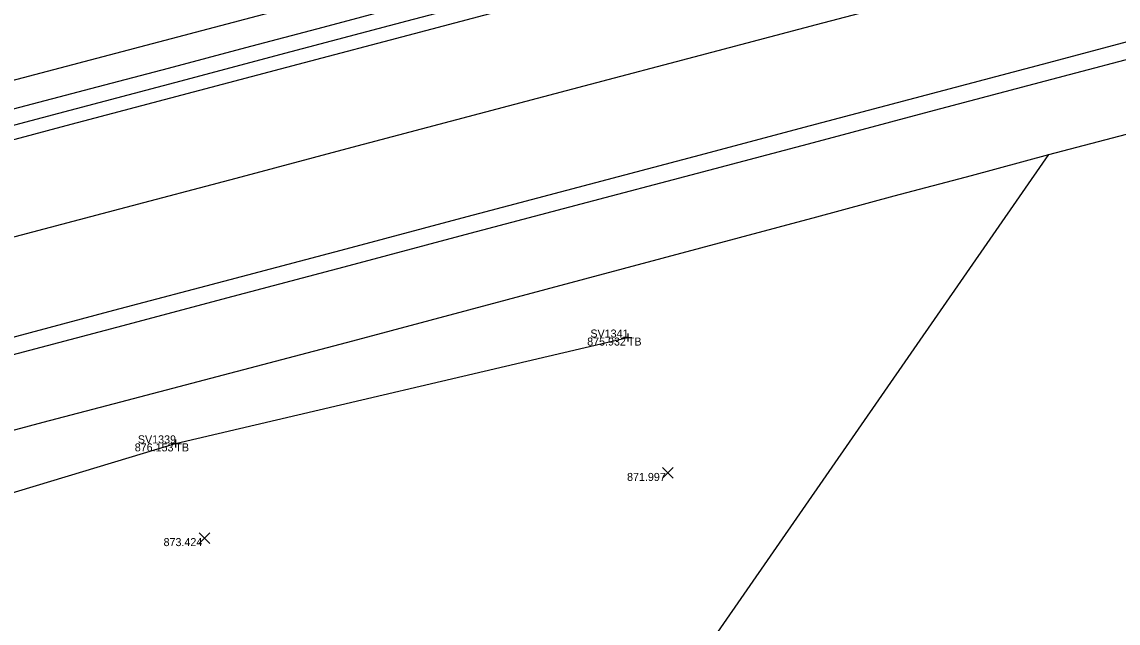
# Model space of a CAD drawing. Extents: x 2125299 to 2129212, y 713100 to 714300.
# Drawn here: x 2128517.6 to 2128654.5, y 713974 to 714049.1 of the extents above; entities that cross this region are included whole.
import ezdxf

# ---------------------------------------------------------------- set-up
doc = ezdxf.new("R2010")
doc.units = 0
for name, color, linetype in [('_CIVIL_CONSTRUCTION', 7, 'Continuous'), ('DT_X_Terrain_Boundary', 7, 'Continuous'), ('PV_X_EOP', 7, 'Continuous'), ('PV_X_Shoulder_Rumble_Strip', 7, 'Continuous'), ('RW_P_Esmt_TMP', 7, 'Continuous'), ('RW_X_Esmt_CH', 7, 'Continuous'), ('RW_X_Fee_WL', 7, 'Continuous'), ('SC_Scratch2', 7, 'Continuous'), ('SV_X_Mon_Cells_Found', 7, 'Continuous'), ('SV_X_Text_Elevation', 7, 'Continuous'), ('SV_X_Top_of_Bank', 7, 'Continuous')]:
    doc.layers.add(name, color=color, linetype=linetype)

msp = doc.modelspace()

# ---------------------------------------------------------------- linework, layer by layer
at = {"layer": '_CIVIL_CONSTRUCTION'}
msp.add_lwpolyline([(2128413.82, 713995), (2128428.32, 713998.85), (2128442.82, 714002.69), (2128457.31, 714006.53), (2128471.81, 714010.37), (2128486.31, 714014.22), (2128500.81, 714018.06), (2128515.31, 714021.9), (2128529.81, 714025.74), (2128544.31, 714029.58), (2128558.81, 714033.42), (2128573.31, 714037.26), (2128587.81, 714041.1), (2128602.31, 714044.94), (2128616.82, 714048.77), (2128631.32, 714052.61), (2128645.82, 714056.45), (2128660.32, 714060.29)], dxfattribs=at)
at = {"layer": 'DT_X_Terrain_Boundary'}
msp.add_lwpolyline([(2128604.48, 713972.86), (2128645.85, 714032.51), (2128655.52, 714035.07)], dxfattribs=at)
at = {"layer": 'PV_X_EOP'}
for points in [[(2128516.52, 714038.23), (2128526.19, 714040.77), (2128535.86, 714043.32), (2128545.53, 714045.87), (2128555.19, 714048.42), (2128564.85, 714051.02), (2128574.51, 714053.62), (2128584.16, 714056.22), (2128593.82, 714058.82), (2128603.47, 714061.44), (2128613.12, 714064.08), (2128622.76, 714066.71), (2128632.42, 714069.3), (2128642.1, 714071.81), (2128651.78, 714074.32), (2128661.46, 714076.82)], [(2128510.56, 713996.52), (2128520.23, 713999.07), (2128529.9, 714001.62), (2128539.57, 714004.17), (2128549.24, 714006.71), (2128558.91, 714009.26), (2128568.57, 714011.82), (2128578.23, 714014.4), (2128587.89, 714016.99), (2128597.55, 714019.58), (2128607.21, 714022.16), (2128616.87, 714024.75), (2128626.53, 714027.34), (2128636.19, 714029.92), (2128645.85, 714032.51), (2128655.52, 714035.07)]]:
    msp.add_lwpolyline(points, dxfattribs=at)
at = {"layer": 'PV_X_Shoulder_Rumble_Strip'}
for points in [[(2128406.18, 714006.98), (2128420.68, 714010.82), (2128435.18, 714014.66), (2128449.68, 714018.5), (2128464.18, 714022.34), (2128478.68, 714026.18), (2128493.18, 714030.02), (2128507.68, 714033.86), (2128522.18, 714037.69), (2128536.68, 714041.53), (2128551.18, 714045.37), (2128565.68, 714049.2), (2128580.18, 714053.04), (2128594.68, 714056.88), (2128609.19, 714060.72), (2128623.69, 714064.55), (2128638.19, 714068.39), (2128652.69, 714072.23), (2128667.19, 714076.06)], [(2128413.44, 713980.24), (2128427.94, 713984.07), (2128442.44, 713987.91), (2128456.94, 713991.75), (2128471.44, 713995.6), (2128485.94, 713999.44), (2128500.44, 714003.29), (2128514.94, 714007.13), (2128529.44, 714010.97), (2128543.94, 714014.82), (2128558.44, 714018.66), (2128572.93, 714022.51), (2128587.43, 714026.35), (2128601.93, 714030.2), (2128616.43, 714034.04), (2128630.93, 714037.88), (2128645.43, 714041.73), (2128659.93, 714045.57)]]:
    msp.add_lwpolyline(points, dxfattribs=at)
at = {"layer": 'SC_Scratch2'}
for points in [[(2128407.09, 714005.42), (2128421.59, 714009.26), (2128436.09, 714013.1), (2128450.59, 714016.94), (2128465.09, 714020.78), (2128479.59, 714024.62), (2128494.09, 714028.45), (2128508.59, 714032.29), (2128523.09, 714036.13), (2128537.59, 714039.96), (2128552.09, 714043.8), (2128566.59, 714047.64), (2128581.09, 714051.48), (2128595.59, 714055.31), (2128610.09, 714059.15), (2128624.6, 714062.99), (2128639.1, 714066.82), (2128653.6, 714070.66), (2128668.1, 714074.5)], [(2128413.06, 713982.34), (2128427.56, 713986.17), (2128442.06, 713990), (2128456.56, 713993.85), (2128471.06, 713997.69), (2128485.56, 714001.53), (2128500.06, 714005.38), (2128514.56, 714009.22), (2128529.06, 714013.07), (2128543.56, 714016.91), (2128558.06, 714020.76), (2128572.55, 714024.6), (2128587.05, 714028.45), (2128601.55, 714032.29), (2128616.05, 714036.13), (2128630.55, 714039.98), (2128645.05, 714043.82), (2128659.55, 714047.67)]]:
    msp.add_lwpolyline(points, dxfattribs=at)
at = {"layer": 'SV_X_Mon_Cells_Found'}
for p, q in [((2128593.25, 714010.16), (2128593.25, 714009.16)), ((2128592.75, 714009.66), (2128593.75, 714009.66)), ((2128593.25, 714009.66), (2128593.25, 714009.66)), ((2128536.23, 713996.44), (2128537.23, 713996.44)), ((2128536.73, 713996.94), (2128536.73, 713995.94)), ((2128536.73, 713996.44), (2128536.73, 713996.44))]:
    msp.add_line(p, q, dxfattribs=at)
at = {"layer": 'SV_X_Text_Elevation'}
for p, q in [((2128597.58, 713992.08), (2128598.92, 713993.42)), ((2128597.58, 713993.42), (2128598.92, 713992.08)), ((2128539.72, 713983.94), (2128541.05, 713985.28)), ((2128539.72, 713985.28), (2128541.05, 713983.94))]:
    msp.add_line(p, q, dxfattribs=at)
at = {"layer": 'SV_X_Top_of_Bank'}
for points in [[(2128641.06, 714074.44), (2128591.12, 714062.19), (2128554.7, 714051.88), (2128508.37, 714039.66), (2128452.53, 714024.9), (2128402.4, 714011.79), (2128346.92, 713996.07), (2128287.48, 713981.18), (2128247.17, 713969.96), (2128213.74, 713962.2), (2128176.95, 713953.14), (2128149.75, 713946.28), (2128088.07, 713932.71), (2128089.34, 713952.15), (2128089.79, 713973.52), (2128093.27, 713996.96)], [(2128074.37, 713874.69), (2128142.8, 713890.6), (2128198.94, 713905.19), (2128254.99, 713920.63), (2128306.24, 713935.17), (2128365.05, 713950.7), (2128425.17, 713967.42), (2128484.19, 713980.57), (2128536.73, 713996.44), (2128593.25, 714009.66)]]:
    msp.add_lwpolyline(points, dxfattribs=at)

# ---------------------------------------------------------------- texts
at = {"layer": 'RW_P_Esmt_TMP'}
for p in [(2128593.25, 714008.66), (2128536.73, 713995.44)]:
    msp.add_text('TB', height=1, dxfattribs=at).set_placement(p)
at = {"layer": 'RW_X_Esmt_CH'}
for s, p in [('SV1341', (2128588.57, 714009.66)), ('SV1339', (2128532.05, 713996.44))]:
    msp.add_text(s, height=1, dxfattribs=at).set_placement(p)
at = {"layer": 'RW_X_Fee_WL'}
for s, p in [('875.932', (2128588.17, 714008.66)), ('876.153', (2128531.66, 713995.44)), ('871.997', (2128593.15, 713991.75)), ('873.424', (2128535.26, 713983.61))]:
    msp.add_text(s, height=1, dxfattribs=at).set_placement(p)

doc.saveas('drawing.dxf')
